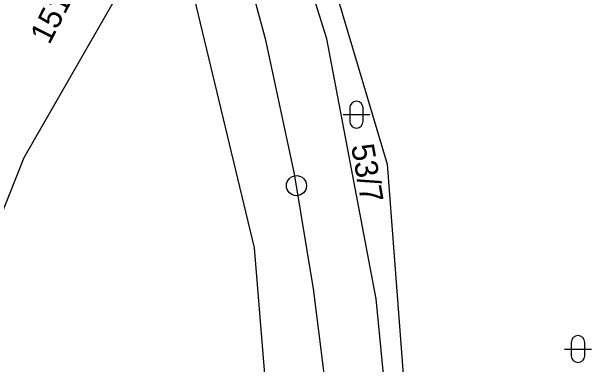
# Model space of a CAD drawing. Extents: x -553916 to -552953, y -1067470 to -1066637.
# Drawn here: x -553527.29 to -553484.03, y -1067025.62 to -1066999.25 of the extents above; entities that cross this region are included whole.
import ezdxf

# ---------------------------------------------------------------- set-up
doc = ezdxf.new("R2010")
doc.units = 0
for name, color, linetype in [('Hranice parcel', 7, 'Continuous'), ('Kolej', 7, 'Continuous'), ('Návěst místo trati', 7, 'Continuous'), ('Parcelní čísla', 7, 'Continuous'), ('Propustek', 7, 'Continuous'), ('Vrstva 1', 7, 'Continuous'), ('Značky kultur', 7, 'Continuous')]:
    doc.layers.add(name, color=color, linetype=linetype)

msp = doc.modelspace()

# ---------------------------------------------------------------- linework, layer by layer
at = {"layer": 'Hranice parcel'}
msp.add_lwpolyline([(-553515.43, -1066991.08), (-553526.38, -1067010.19), (-553539.65, -1067043.59), (-553548.33, -1067069.03)], dxfattribs=at)
at = {"layer": 'Kolej'}
msp.add_lwpolyline([(-553503.324, -1067065.808), (-553502.678, -1067054.027), (-553502.762, -1067041.504), (-553503.626, -1067029.057), (-553504.756, -1067019.974), (-553506.183, -1067011.388), (-553508.328, -1067001.388), (-553510.948, -1066991.622), (-553512.921, -1066985.291), (-553515.647, -1066977.347), (-553517.422, -1066972.53), (-553519.157, -1066967.95), (-553522.886, -1066958.375), (-553529.101, -1066942.549), (-553538.686, -1066918.107), (-553542.908, -1066907.329), (-553546.692, -1066897.676), (-553555.025, -1066876.441), (-553564.644, -1066851.894), (-553574.241, -1066827.427), (-553583.19, -1066804.618)], dxfattribs=at)
at = {"layer": 'Návěst místo trati'}
msp.add_circle((-553506.038, -1067012.26), 0.75, dxfattribs=at)
at = {"layer": 'Propustek'}
for p, q in [((-553505.83, -1066988.51), (-553499.28, -1067010.65)), ((-553499.28, -1067010.65), (-553496.78, -1067043.02))]:
    msp.add_line(p, q, dxfattribs=at)
for points in [[(-553498.68, -1067074.42), (-553498.17, -1067040.43), (-553500.08, -1067020.73), (-553503.77, -1067001.28), (-553507.63, -1066988.97), (-553505.83, -1066988.51)], [(-553509.03, -1067072.35), (-553507.22, -1067040.68), (-553509.18, -1067016.9), (-553515.22, -1066991.69), (-553515.43, -1066991.08)]]:
    msp.add_lwpolyline(points, dxfattribs=at)
at = {"layer": 'Značky kultur'}
for p, q in [((-553502.06, -1067006.453), (-553502.06, -1067007.454)), ((-553501.058, -1067007.454), (-553501.058, -1067006.453)), ((-553502.56, -1067006.953), (-553500.558, -1067006.953)), ((-553485.531, -1067023.971), (-553485.531, -1067024.972)), ((-553484.529, -1067024.972), (-553484.529, -1067023.971)), ((-553486.031, -1067024.471), (-553484.029, -1067024.471))]:
    msp.add_line(p, q, dxfattribs=at)
for centre, start, end in [((-553501.559, -1067006.453), 0, 180), ((-553501.559, -1067007.453), 180, 359.9879), ((-553485.03, -1067023.971), 0, 180), ((-553485.03, -1067024.971), 180, 359.9879)]:
    msp.add_arc(centre, 0.5, start, end, dxfattribs=at)

# ---------------------------------------------------------------- texts
at = {"layer": 'Parcelní čísla'}
msp.add_text('1517/7', height=1.7, rotation=63, dxfattribs=at).set_placement((-553524.481, -1067001.782))
at = {"layer": 'Vrstva 1'}
msp.add_text('53/7', height=1.7, rotation=280, dxfattribs=at).set_placement((-553501.965, -1067009.286))

doc.saveas('drawing.dxf')
